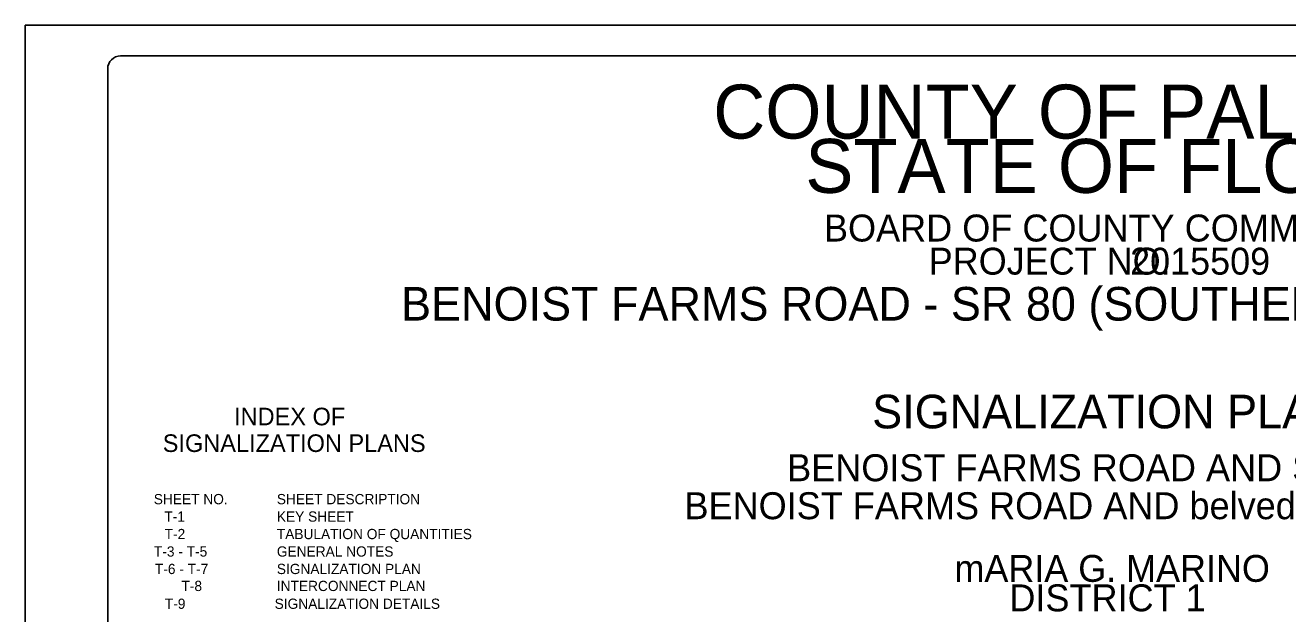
# Model space of a CAD drawing. Extents: x 801329 to 1085229, y 842463 to 1044570.
# Drawn here: x 801329 to 967224, y 945308 to 1022663 of the extents above; entities that cross this region are included whole.
import ezdxf

# ---------------------------------------------------------------- set-up
doc = ezdxf.new("R2010")
doc.units = 0
for name, color, linetype in [('Default', 7, 'Continuous'), ('PlotBorder_dp', 7, 'Continuous'), ('TextLabel', 7, 'Continuous')]:
    doc.layers.add(name, color=color, linetype=linetype)

msp = doc.modelspace()

# ---------------------------------------------------------------- linework, layer by layer
at = {"layer": 'Default'}
for p, q in [((813867, 1018625), (1063315, 1018625)), ((812167, 845650), (812167, 1016925))]:
    msp.add_line(p, q, dxfattribs=at)
msp.add_arc((813867, 1016925), 1700, 90, 180, dxfattribs=at)
at = {"layer": 'PlotBorder_dp'}
msp.add_lwpolyline([(801329, 842463), (1085229, 842463), (1085229, 1022663), (801329, 1022663)], close=True, dxfattribs=at)

# ---------------------------------------------------------------- texts
at = {"layer": 'Default'}
for s, height, p in [('SIGNALIZATION PLANS', 4419.99, (912618, 969676)), ('INDEX OF ', 2312.8, (828768, 970077)), ('SIGNALIZATION PLANS', 2312.85, (819395, 966574)), ('SHEET NO.', 1348.1, (818216, 959704)), ('SHEET DESCRIPTION                  ', 1347.67, (834388, 959704)), ('   T-1   ', 1348.1, (818113, 957409)), ('KEY SHEET                          ', 1347.67, (834388, 957409)), ('   T-2   ', 1348.1, (818143, 955114)), ('TABULATION OF QUANTITIES           ', 1347.67, (834388, 955114)), ('T-3 - T-5', 1348.1, (818236, 952819)), ('GENERAL NOTES                      ', 1347.67, (834388, 952819)), ('T-6 - T-7', 1348.1, (818365, 950524)), ('SIGNALIZATION PLAN                 ', 1347.67, (834388, 950524)), ('T-8', 1348.1, (821860, 948293)), ('INTERCONNECT PLAN                  ', 1347.67, (834388, 948293)), ('   T-9   ', 1348.1, (818171, 945952)), ('SIGNALIZATION DETAILS', 1347.67, (834102, 945952))]:
    msp.add_text(s, height=height, dxfattribs=at).set_placement(p)
at = {"layer": 'TextLabel'}
for s, height, p in [('COUNTY OF PALM BEACH', 7090.68, (891724, 1007768)), ('STATE OF FLORIDA', 7090.68, (903829, 1000628)), ('BOARD OF COUNTY COMMISSIONERS', 3544.49, (906281, 994236)), ('PROJECT NO.', 3535.99, (920048, 989884)), ('2015509           ', 3535.99, (946504, 989884)), ('BENOIST FARMS ROAD - SR 80 (SOUTHERN BOULEVARD) TO BELVEDERE ROAD', 4419.99, (850713, 983842)), ('BENOIST FARMS ROAD AND SR 80 (Ts-30800)', 3544.49, (901443, 962727)), ('BENOIST FARMS ROAD AND belvedere road (Ts-29055-a)', 3544.49, (887950, 957738)), ('mARIA G. MARINO', 3530.89, (923429, 949504)), ('DISTRICT 1', 3544.5, (930643, 945628))]:
    msp.add_text(s, height=height, dxfattribs=at).set_placement(p)

doc.saveas('drawing.dxf')
